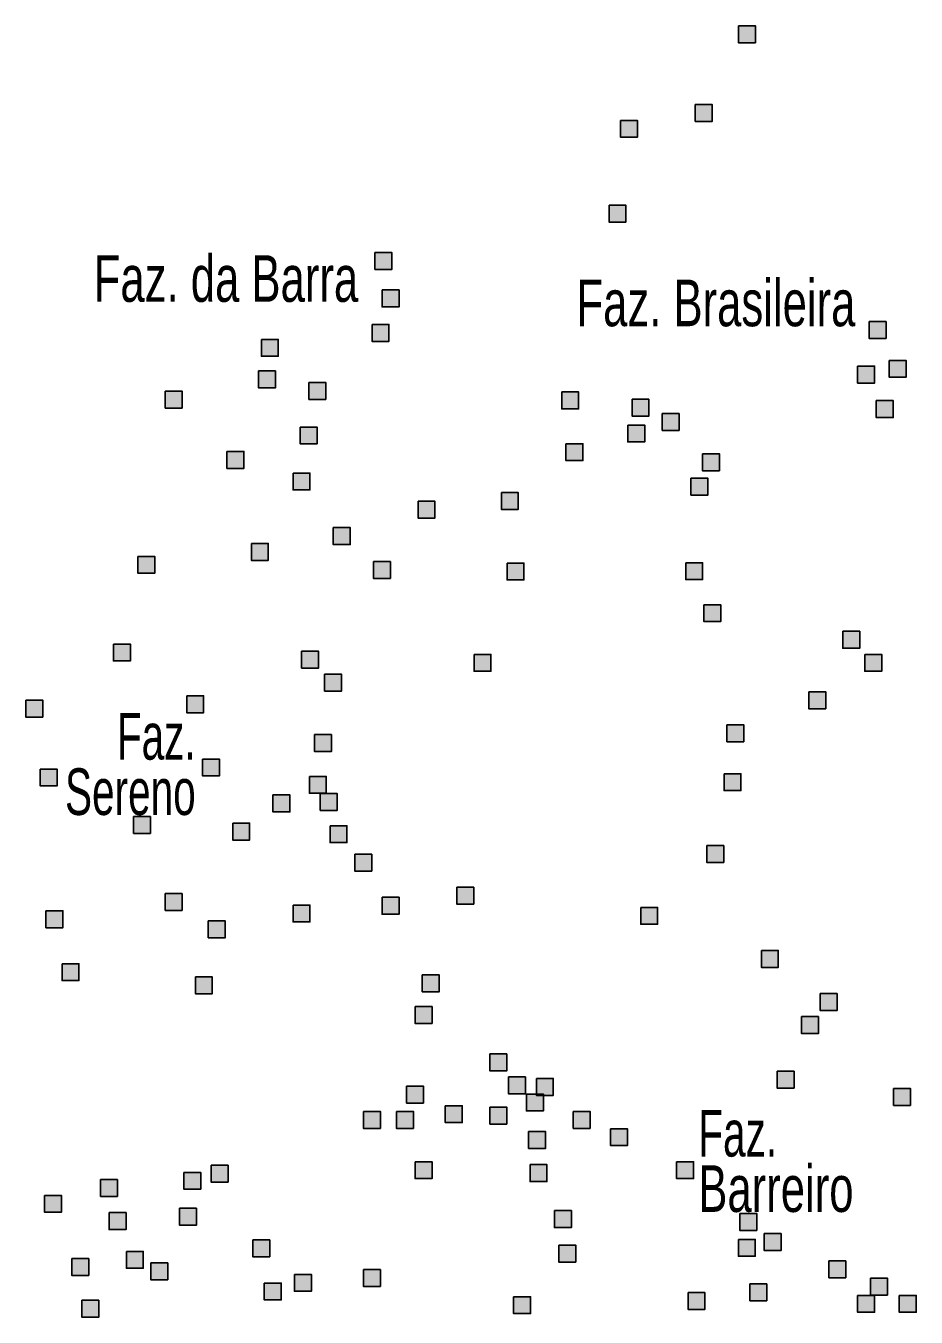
# Model space of a CAD drawing. Extents: x 445.4 to 500, y 8728.7 to 8784.
# Drawn here: x 488.568 to 491.623, y 8728.707 to 8733.138 of the extents above; entities that cross this region are included whole.
import ezdxf
from ezdxf.enums import TextEntityAlignment as Align

# ---------------------------------------------------------------- set-up
doc = ezdxf.new("R2010")
doc.units = 0
doc.header["$LTSCALE"] = 0.064
doc.layers.add('2', color=7, linetype='Continuous', lineweight=25)
doc.layers.add('61', color=7, linetype='Continuous')

msp = doc.modelspace()

# ---------------------------------------------------------------- hatches: boundary and pattern name
at = {"layer": '2'}
for points in [[(491.0138, 8733.1381), (491.0718, 8733.1381), (491.0718, 8733.0801), (491.0138, 8733.0801)], [(490.8656, 8732.868), (490.9236, 8732.868), (490.9236, 8732.81), (490.8656, 8732.81)], [(490.6093, 8732.8137), (490.6673, 8732.8137), (490.6673, 8732.7557), (490.6093, 8732.7557)], [(490.5698, 8732.5227), (490.6278, 8732.5227), (490.6278, 8732.4647), (490.5698, 8732.4647)], [(489.7664, 8732.36), (489.8244, 8732.36), (489.8244, 8732.302), (489.7664, 8732.302)], [(489.791, 8732.2318), (489.849, 8732.2318), (489.849, 8732.1738), (489.791, 8732.1738)], [(491.462, 8732.1233), (491.52, 8732.1233), (491.52, 8732.0653), (491.462, 8732.0653)], [(489.7565, 8732.1134), (489.8145, 8732.1134), (489.8145, 8732.0554), (489.7565, 8732.0554)], [(489.3769, 8732.0622), (489.4349, 8732.0622), (489.4349, 8732.0042), (489.3769, 8732.0042)], [(491.531, 8731.9901), (491.589, 8731.9901), (491.589, 8731.9321), (491.531, 8731.9321)], [(489.3671, 8731.9537), (489.4251, 8731.9537), (489.4251, 8731.8957), (489.3671, 8731.8957)], [(491.4226, 8731.9704), (491.4806, 8731.9704), (491.4806, 8731.9124), (491.4226, 8731.9124)], [(489.5396, 8731.9142), (489.5976, 8731.9142), (489.5976, 8731.8562), (489.5396, 8731.8562)], [(489.0467, 8731.8846), (489.1047, 8731.8846), (489.1047, 8731.8266), (489.0467, 8731.8266)], [(490.4072, 8731.8816), (490.4652, 8731.8816), (490.4652, 8731.8236), (490.4072, 8731.8236)], [(490.6487, 8731.857), (490.7067, 8731.857), (490.7067, 8731.799), (490.6487, 8731.799)], [(491.4867, 8731.852), (491.5447, 8731.852), (491.5447, 8731.794), (491.4867, 8731.794)], [(490.7522, 8731.8076), (490.8102, 8731.8076), (490.8102, 8731.7496), (490.7522, 8731.7496)], [(489.51, 8731.7613), (489.568, 8731.7613), (489.568, 8731.7033), (489.51, 8731.7033)], [(490.6339, 8731.7682), (490.6919, 8731.7682), (490.6919, 8731.7102), (490.6339, 8731.7102)], [(490.4219, 8731.7041), (490.4799, 8731.7041), (490.4799, 8731.6461), (490.4219, 8731.6461)], [(489.2586, 8731.6775), (489.3166, 8731.6775), (489.3166, 8731.6195), (489.2586, 8731.6195)], [(490.8902, 8731.6696), (490.9482, 8731.6696), (490.9482, 8731.6116), (490.8902, 8731.6116)], [(489.4854, 8731.6035), (489.5434, 8731.6035), (489.5434, 8731.5455), (489.4854, 8731.5455)], [(490.8508, 8731.5857), (490.9088, 8731.5857), (490.9088, 8731.5277), (490.8508, 8731.5277)], [(489.9142, 8731.5068), (489.9722, 8731.5068), (489.9722, 8731.4488), (489.9142, 8731.4488)], [(490.2001, 8731.5364), (490.2581, 8731.5364), (490.2581, 8731.4784), (490.2001, 8731.4784)], [(489.6234, 8731.4161), (489.6814, 8731.4161), (489.6814, 8731.3581), (489.6234, 8731.3581)], [(489.3424, 8731.3619), (489.4004, 8731.3619), (489.4004, 8731.3039), (489.3424, 8731.3039)], [(488.953, 8731.3175), (489.011, 8731.3175), (489.011, 8731.2595), (488.953, 8731.2595)], [(489.7614, 8731.2997), (489.8194, 8731.2997), (489.8194, 8731.2417), (489.7614, 8731.2417)], [(490.2198, 8731.2948), (490.2778, 8731.2948), (490.2778, 8731.2368), (490.2198, 8731.2368)], [(490.8329, 8731.2957), (490.8909, 8731.2957), (490.8909, 8731.2377), (490.8329, 8731.2377)], [(490.8952, 8731.1517), (490.9532, 8731.1517), (490.9532, 8731.0937), (490.8952, 8731.0937)], [(491.3717, 8731.0605), (491.4297, 8731.0605), (491.4297, 8731.0025), (491.3717, 8731.0025)], [(488.8692, 8731.0166), (488.9272, 8731.0166), (488.9272, 8730.9586), (488.8692, 8730.9586)], [(489.5149, 8730.992), (489.5729, 8730.992), (489.5729, 8730.934), (489.5149, 8730.934)], [(490.1065, 8730.9811), (490.1645, 8730.9811), (490.1645, 8730.9231), (490.1065, 8730.9231)], [(491.4472, 8730.9811), (491.5052, 8730.9811), (491.5052, 8730.9231), (491.4472, 8730.9231)], [(489.5938, 8730.9131), (489.6518, 8730.9131), (489.6518, 8730.8551), (489.5938, 8730.8551)], [(489.1206, 8730.8391), (489.1786, 8730.8391), (489.1786, 8730.7811), (489.1206, 8730.7811)], [(491.255, 8730.8529), (491.313, 8730.8529), (491.313, 8730.7949), (491.255, 8730.7949)], [(488.5685, 8730.8243), (488.6265, 8730.8243), (488.6265, 8730.7663), (488.5685, 8730.7663)], [(489.5593, 8730.7059), (489.6173, 8730.7059), (489.6173, 8730.6479), (489.5593, 8730.6479)], [(490.974, 8730.7395), (491.032, 8730.7395), (491.032, 8730.6815), (490.974, 8730.6815)], [(489.1748, 8730.6221), (489.2328, 8730.6221), (489.2328, 8730.5641), (489.1748, 8730.5641)], [(488.6178, 8730.5876), (488.6758, 8730.5876), (488.6758, 8730.5296), (488.6178, 8730.5296)], [(489.5414, 8730.5627), (489.5994, 8730.5627), (489.5994, 8730.5047), (489.5414, 8730.5047)], [(490.9642, 8730.5718), (491.0222, 8730.5718), (491.0222, 8730.5138), (490.9642, 8730.5138)], [(489.4164, 8730.4988), (489.4744, 8730.4988), (489.4744, 8730.4408), (489.4164, 8730.4408)], [(489.579, 8730.5037), (489.637, 8730.5037), (489.637, 8730.4457), (489.579, 8730.4457)], [(488.9382, 8730.4248), (488.9962, 8730.4248), (488.9962, 8730.3668), (488.9382, 8730.3668)], [(489.2783, 8730.4022), (489.3363, 8730.4022), (489.3363, 8730.3442), (489.2783, 8730.3442)], [(489.6124, 8730.3932), (489.6704, 8730.3932), (489.6704, 8730.3352), (489.6124, 8730.3352)], [(490.905, 8730.3252), (490.963, 8730.3252), (490.963, 8730.2672), (490.905, 8730.2672)], [(489.6973, 8730.2956), (489.7553, 8730.2956), (489.7553, 8730.2376), (489.6973, 8730.2376)], [(490.0473, 8730.1822), (490.1053, 8730.1822), (490.1053, 8730.1242), (490.0473, 8730.1242)], [(489.0467, 8730.1605), (489.1047, 8730.1605), (489.1047, 8730.1025), (489.0467, 8730.1025)], [(489.791, 8730.1477), (489.849, 8730.1477), (489.849, 8730.0897), (489.791, 8730.0897)], [(488.6375, 8730.1013), (488.6955, 8730.1013), (488.6955, 8730.0433), (488.6375, 8730.0433)], [(489.4854, 8730.1211), (489.5434, 8730.1211), (489.5434, 8730.0631), (489.4854, 8730.0631)], [(490.6783, 8730.1131), (490.7363, 8730.1131), (490.7363, 8730.0551), (490.6783, 8730.0551)], [(489.1945, 8730.0668), (489.2525, 8730.0668), (489.2525, 8730.0088), (489.1945, 8730.0088)], [(491.0923, 8729.9652), (491.1503, 8729.9652), (491.1503, 8729.9072), (491.0923, 8729.9072)], [(488.6929, 8729.9198), (488.7509, 8729.9198), (488.7509, 8729.8618), (488.6929, 8729.8618)], [(489.1502, 8729.8745), (489.2082, 8729.8745), (489.2082, 8729.8165), (489.1502, 8729.8165)], [(489.929, 8729.8814), (489.987, 8729.8814), (489.987, 8729.8234), (489.929, 8729.8234)], [(491.2944, 8729.8172), (491.3524, 8729.8172), (491.3524, 8729.7592), (491.2944, 8729.7592)], [(489.9044, 8729.7729), (489.9624, 8729.7729), (489.9624, 8729.7149), (489.9044, 8729.7149)], [(491.2303, 8729.7383), (491.2883, 8729.7383), (491.2883, 8729.6803), (491.2303, 8729.6803)], [(490.1607, 8729.6101), (490.2187, 8729.6101), (490.2187, 8729.5521), (490.1607, 8729.5521)], [(490.2248, 8729.5312), (490.2828, 8729.5312), (490.2828, 8729.4732), (490.2248, 8729.4732)], [(490.3204, 8729.526), (490.3784, 8729.526), (490.3784, 8729.468), (490.3204, 8729.468)], [(491.1465, 8729.5509), (491.2045, 8729.5509), (491.2045, 8729.4929), (491.1465, 8729.4929)], [(489.8748, 8729.4996), (489.9328, 8729.4996), (489.9328, 8729.4416), (489.8748, 8729.4416)], [(490.2862, 8729.4726), (490.3442, 8729.4726), (490.3442, 8729.4146), (490.2862, 8729.4146)], [(491.5458, 8729.4918), (491.6038, 8729.4918), (491.6038, 8729.4338), (491.5458, 8729.4338)], [(490.0079, 8729.4326), (490.0659, 8729.4326), (490.0659, 8729.3746), (490.0079, 8729.3746)], [(490.1607, 8729.4276), (490.2187, 8729.4276), (490.2187, 8729.3696), (490.1607, 8729.3696)], [(489.7269, 8729.4128), (489.7849, 8729.4128), (489.7849, 8729.3548), (489.7269, 8729.3548)], [(489.8403, 8729.4128), (489.8983, 8729.4128), (489.8983, 8729.3548), (489.8403, 8729.3548)], [(490.4466, 8729.4128), (490.5046, 8729.4128), (490.5046, 8729.3548), (490.4466, 8729.3548)], [(490.2938, 8729.3438), (490.3518, 8729.3438), (490.3518, 8729.2858), (490.2938, 8729.2858)], [(490.5748, 8729.3537), (490.6328, 8729.3537), (490.6328, 8729.2957), (490.5748, 8729.2957)], [(489.1107, 8729.2038), (489.1687, 8729.2038), (489.1687, 8729.1458), (489.1107, 8729.1458)], [(489.2044, 8729.2284), (489.2624, 8729.2284), (489.2624, 8729.1704), (489.2044, 8729.1704)], [(489.9044, 8729.2402), (489.9624, 8729.2402), (489.9624, 8729.1822), (489.9044, 8729.1822)], [(490.2987, 8729.2304), (490.3567, 8729.2304), (490.3567, 8729.1724), (490.2987, 8729.1724)], [(490.8015, 8729.2402), (490.8595, 8729.2402), (490.8595, 8729.1822), (490.8015, 8729.1822)], [(488.8248, 8729.1791), (488.8828, 8729.1791), (488.8828, 8729.1211), (488.8248, 8729.1211)], [(488.6326, 8729.1249), (488.6906, 8729.1249), (488.6906, 8729.0669), (488.6326, 8729.0669)], [(488.8544, 8729.0657), (488.9124, 8729.0657), (488.9124, 8729.0077), (488.8544, 8729.0077)], [(489.096, 8729.0805), (489.154, 8729.0805), (489.154, 8729.0225), (489.096, 8729.0225)], [(490.3825, 8729.0726), (490.4405, 8729.0726), (490.4405, 8729.0146), (490.3825, 8729.0146)], [(491.0184, 8729.0627), (491.0764, 8729.0627), (491.0764, 8729.0047), (491.0184, 8729.0047)], [(491.1022, 8728.9936), (491.1602, 8728.9936), (491.1602, 8728.9356), (491.1022, 8728.9356)], [(488.9136, 8728.9325), (488.9716, 8728.9325), (488.9716, 8728.8745), (488.9136, 8728.8745)], [(489.3473, 8728.972), (489.4053, 8728.972), (489.4053, 8728.914), (489.3473, 8728.914)], [(490.3973, 8728.9542), (490.4553, 8728.9542), (490.4553, 8728.8962), (490.3973, 8728.8962)], [(491.0135, 8728.9739), (491.0715, 8728.9739), (491.0715, 8728.9159), (491.0135, 8728.9159)], [(488.7263, 8728.9079), (488.7843, 8728.9079), (488.7843, 8728.8499), (488.7263, 8728.8499)], [(488.9974, 8728.8931), (489.0554, 8728.8931), (489.0554, 8728.8351), (488.9974, 8728.8351)], [(491.324, 8728.8999), (491.382, 8728.8999), (491.382, 8728.8419), (491.324, 8728.8419)], [(489.4903, 8728.8536), (489.5483, 8728.8536), (489.5483, 8728.7956), (489.4903, 8728.7956)], [(489.7269, 8728.8704), (489.7849, 8728.8704), (489.7849, 8728.8124), (489.7269, 8728.8124)], [(489.3868, 8728.824), (489.4448, 8728.824), (489.4448, 8728.766), (489.3868, 8728.766)], [(491.0529, 8728.821), (491.1109, 8728.821), (491.1109, 8728.763), (491.0529, 8728.763)], [(491.4669, 8728.8408), (491.5249, 8728.8408), (491.5249, 8728.7828), (491.4669, 8728.7828)], [(488.7608, 8728.7649), (488.8188, 8728.7649), (488.8188, 8728.7069), (488.7608, 8728.7069)], [(490.2422, 8728.777), (490.3002, 8728.777), (490.3002, 8728.719), (490.2422, 8728.719)], [(490.8409, 8728.7914), (490.8989, 8728.7914), (490.8989, 8728.7334), (490.8409, 8728.7334)], [(491.4226, 8728.7816), (491.4806, 8728.7816), (491.4806, 8728.7236), (491.4226, 8728.7236)], [(491.5655, 8728.7816), (491.6235, 8728.7816), (491.6235, 8728.7236), (491.5655, 8728.7236)]]:
    msp.add_hatch(color=256, dxfattribs=at).paths.add_polyline_path(points)

# ---------------------------------------------------------------- linework, layer by layer
for points in [[(491.0138, 8733.1381), (491.0718, 8733.1381), (491.0718, 8733.0801), (491.0138, 8733.0801)], [(490.8656, 8732.868), (490.9236, 8732.868), (490.9236, 8732.81), (490.8656, 8732.81)], [(490.6093, 8732.8137), (490.6673, 8732.8137), (490.6673, 8732.7557), (490.6093, 8732.7557)], [(490.5698, 8732.5227), (490.6278, 8732.5227), (490.6278, 8732.4647), (490.5698, 8732.4647)], [(489.7664, 8732.36), (489.8244, 8732.36), (489.8244, 8732.302), (489.7664, 8732.302)], [(489.791, 8732.2318), (489.849, 8732.2318), (489.849, 8732.1738), (489.791, 8732.1738)], [(491.462, 8732.1233), (491.52, 8732.1233), (491.52, 8732.0653), (491.462, 8732.0653)], [(489.7565, 8732.1134), (489.8145, 8732.1134), (489.8145, 8732.0554), (489.7565, 8732.0554)], [(489.3769, 8732.0622), (489.4349, 8732.0622), (489.4349, 8732.0042), (489.3769, 8732.0042)], [(491.531, 8731.9901), (491.589, 8731.9901), (491.589, 8731.9321), (491.531, 8731.9321)], [(489.3671, 8731.9537), (489.4251, 8731.9537), (489.4251, 8731.8957), (489.3671, 8731.8957)], [(491.4226, 8731.9704), (491.4806, 8731.9704), (491.4806, 8731.9124), (491.4226, 8731.9124)], [(489.5396, 8731.9142), (489.5976, 8731.9142), (489.5976, 8731.8562), (489.5396, 8731.8562)], [(489.0467, 8731.8846), (489.1047, 8731.8846), (489.1047, 8731.8266), (489.0467, 8731.8266)], [(490.4072, 8731.8816), (490.4652, 8731.8816), (490.4652, 8731.8236), (490.4072, 8731.8236)], [(490.6487, 8731.857), (490.7067, 8731.857), (490.7067, 8731.799), (490.6487, 8731.799)], [(491.4867, 8731.852), (491.5447, 8731.852), (491.5447, 8731.794), (491.4867, 8731.794)], [(490.7522, 8731.8076), (490.8102, 8731.8076), (490.8102, 8731.7496), (490.7522, 8731.7496)], [(489.51, 8731.7613), (489.568, 8731.7613), (489.568, 8731.7033), (489.51, 8731.7033)], [(490.6339, 8731.7682), (490.6919, 8731.7682), (490.6919, 8731.7102), (490.6339, 8731.7102)], [(490.4219, 8731.7041), (490.4799, 8731.7041), (490.4799, 8731.6461), (490.4219, 8731.6461)], [(489.2586, 8731.6775), (489.3166, 8731.6775), (489.3166, 8731.6195), (489.2586, 8731.6195)], [(490.8902, 8731.6696), (490.9482, 8731.6696), (490.9482, 8731.6116), (490.8902, 8731.6116)], [(489.4854, 8731.6035), (489.5434, 8731.6035), (489.5434, 8731.5455), (489.4854, 8731.5455)], [(490.8508, 8731.5857), (490.9088, 8731.5857), (490.9088, 8731.5277), (490.8508, 8731.5277)], [(489.9142, 8731.5068), (489.9722, 8731.5068), (489.9722, 8731.4488), (489.9142, 8731.4488)], [(490.2001, 8731.5364), (490.2581, 8731.5364), (490.2581, 8731.4784), (490.2001, 8731.4784)], [(489.6234, 8731.4161), (489.6814, 8731.4161), (489.6814, 8731.3581), (489.6234, 8731.3581)], [(489.3424, 8731.3619), (489.4004, 8731.3619), (489.4004, 8731.3039), (489.3424, 8731.3039)], [(488.953, 8731.3175), (489.011, 8731.3175), (489.011, 8731.2595), (488.953, 8731.2595)], [(489.7614, 8731.2997), (489.8194, 8731.2997), (489.8194, 8731.2417), (489.7614, 8731.2417)], [(490.2198, 8731.2948), (490.2778, 8731.2948), (490.2778, 8731.2368), (490.2198, 8731.2368)], [(490.8329, 8731.2957), (490.8909, 8731.2957), (490.8909, 8731.2377), (490.8329, 8731.2377)], [(490.8952, 8731.1517), (490.9532, 8731.1517), (490.9532, 8731.0937), (490.8952, 8731.0937)], [(491.3717, 8731.0605), (491.4297, 8731.0605), (491.4297, 8731.0025), (491.3717, 8731.0025)], [(488.8692, 8731.0166), (488.9272, 8731.0166), (488.9272, 8730.9586), (488.8692, 8730.9586)], [(489.5149, 8730.992), (489.5729, 8730.992), (489.5729, 8730.934), (489.5149, 8730.934)], [(490.1065, 8730.9811), (490.1645, 8730.9811), (490.1645, 8730.9231), (490.1065, 8730.9231)], [(491.4472, 8730.9811), (491.5052, 8730.9811), (491.5052, 8730.9231), (491.4472, 8730.9231)], [(489.5938, 8730.9131), (489.6518, 8730.9131), (489.6518, 8730.8551), (489.5938, 8730.8551)], [(489.1206, 8730.8391), (489.1786, 8730.8391), (489.1786, 8730.7811), (489.1206, 8730.7811)], [(491.255, 8730.8529), (491.313, 8730.8529), (491.313, 8730.7949), (491.255, 8730.7949)], [(488.5685, 8730.8243), (488.6265, 8730.8243), (488.6265, 8730.7663), (488.5685, 8730.7663)], [(489.5593, 8730.7059), (489.6173, 8730.7059), (489.6173, 8730.6479), (489.5593, 8730.6479)], [(490.974, 8730.7395), (491.032, 8730.7395), (491.032, 8730.6815), (490.974, 8730.6815)], [(489.1748, 8730.6221), (489.2328, 8730.6221), (489.2328, 8730.5641), (489.1748, 8730.5641)], [(488.6178, 8730.5876), (488.6758, 8730.5876), (488.6758, 8730.5296), (488.6178, 8730.5296)], [(489.5414, 8730.5627), (489.5994, 8730.5627), (489.5994, 8730.5047), (489.5414, 8730.5047)], [(490.9642, 8730.5718), (491.0222, 8730.5718), (491.0222, 8730.5138), (490.9642, 8730.5138)], [(489.4164, 8730.4988), (489.4744, 8730.4988), (489.4744, 8730.4408), (489.4164, 8730.4408)], [(489.579, 8730.5037), (489.637, 8730.5037), (489.637, 8730.4457), (489.579, 8730.4457)], [(488.9382, 8730.4248), (488.9962, 8730.4248), (488.9962, 8730.3668), (488.9382, 8730.3668)], [(489.2783, 8730.4022), (489.3363, 8730.4022), (489.3363, 8730.3442), (489.2783, 8730.3442)], [(489.6124, 8730.3932), (489.6704, 8730.3932), (489.6704, 8730.3352), (489.6124, 8730.3352)], [(490.905, 8730.3252), (490.963, 8730.3252), (490.963, 8730.2672), (490.905, 8730.2672)], [(489.6973, 8730.2956), (489.7553, 8730.2956), (489.7553, 8730.2376), (489.6973, 8730.2376)], [(490.0473, 8730.1822), (490.1053, 8730.1822), (490.1053, 8730.1242), (490.0473, 8730.1242)], [(489.0467, 8730.1605), (489.1047, 8730.1605), (489.1047, 8730.1025), (489.0467, 8730.1025)], [(489.791, 8730.1477), (489.849, 8730.1477), (489.849, 8730.0897), (489.791, 8730.0897)], [(488.6375, 8730.1013), (488.6955, 8730.1013), (488.6955, 8730.0433), (488.6375, 8730.0433)], [(489.4854, 8730.1211), (489.5434, 8730.1211), (489.5434, 8730.0631), (489.4854, 8730.0631)], [(490.6783, 8730.1131), (490.7363, 8730.1131), (490.7363, 8730.0551), (490.6783, 8730.0551)], [(489.1945, 8730.0668), (489.2525, 8730.0668), (489.2525, 8730.0088), (489.1945, 8730.0088)], [(491.0923, 8729.9652), (491.1503, 8729.9652), (491.1503, 8729.9072), (491.0923, 8729.9072)], [(488.6929, 8729.9198), (488.7509, 8729.9198), (488.7509, 8729.8618), (488.6929, 8729.8618)], [(489.1502, 8729.8745), (489.2082, 8729.8745), (489.2082, 8729.8165), (489.1502, 8729.8165)], [(489.929, 8729.8814), (489.987, 8729.8814), (489.987, 8729.8234), (489.929, 8729.8234)], [(491.2944, 8729.8172), (491.3524, 8729.8172), (491.3524, 8729.7592), (491.2944, 8729.7592)], [(489.9044, 8729.7729), (489.9624, 8729.7729), (489.9624, 8729.7149), (489.9044, 8729.7149)], [(491.2303, 8729.7383), (491.2883, 8729.7383), (491.2883, 8729.6803), (491.2303, 8729.6803)], [(490.1607, 8729.6101), (490.2187, 8729.6101), (490.2187, 8729.5521), (490.1607, 8729.5521)], [(490.2248, 8729.5312), (490.2828, 8729.5312), (490.2828, 8729.4732), (490.2248, 8729.4732)], [(490.3204, 8729.526), (490.3784, 8729.526), (490.3784, 8729.468), (490.3204, 8729.468)], [(491.1465, 8729.5509), (491.2045, 8729.5509), (491.2045, 8729.4929), (491.1465, 8729.4929)], [(489.8748, 8729.4996), (489.9328, 8729.4996), (489.9328, 8729.4416), (489.8748, 8729.4416)], [(490.2862, 8729.4726), (490.3442, 8729.4726), (490.3442, 8729.4146), (490.2862, 8729.4146)], [(491.5458, 8729.4918), (491.6038, 8729.4918), (491.6038, 8729.4338), (491.5458, 8729.4338)], [(490.0079, 8729.4326), (490.0659, 8729.4326), (490.0659, 8729.3746), (490.0079, 8729.3746)], [(490.1607, 8729.4276), (490.2187, 8729.4276), (490.2187, 8729.3696), (490.1607, 8729.3696)], [(489.7269, 8729.4128), (489.7849, 8729.4128), (489.7849, 8729.3548), (489.7269, 8729.3548)], [(489.8403, 8729.4128), (489.8983, 8729.4128), (489.8983, 8729.3548), (489.8403, 8729.3548)], [(490.4466, 8729.4128), (490.5046, 8729.4128), (490.5046, 8729.3548), (490.4466, 8729.3548)], [(490.2938, 8729.3438), (490.3518, 8729.3438), (490.3518, 8729.2858), (490.2938, 8729.2858)], [(490.5748, 8729.3537), (490.6328, 8729.3537), (490.6328, 8729.2957), (490.5748, 8729.2957)], [(489.1107, 8729.2038), (489.1687, 8729.2038), (489.1687, 8729.1458), (489.1107, 8729.1458)], [(489.2044, 8729.2284), (489.2624, 8729.2284), (489.2624, 8729.1704), (489.2044, 8729.1704)], [(489.9044, 8729.2402), (489.9624, 8729.2402), (489.9624, 8729.1822), (489.9044, 8729.1822)], [(490.2987, 8729.2304), (490.3567, 8729.2304), (490.3567, 8729.1724), (490.2987, 8729.1724)], [(490.8015, 8729.2402), (490.8595, 8729.2402), (490.8595, 8729.1822), (490.8015, 8729.1822)], [(488.8248, 8729.1791), (488.8828, 8729.1791), (488.8828, 8729.1211), (488.8248, 8729.1211)], [(488.6326, 8729.1249), (488.6906, 8729.1249), (488.6906, 8729.0669), (488.6326, 8729.0669)], [(488.8544, 8729.0657), (488.9124, 8729.0657), (488.9124, 8729.0077), (488.8544, 8729.0077)], [(489.096, 8729.0805), (489.154, 8729.0805), (489.154, 8729.0225), (489.096, 8729.0225)], [(490.3825, 8729.0726), (490.4405, 8729.0726), (490.4405, 8729.0146), (490.3825, 8729.0146)], [(491.0184, 8729.0627), (491.0764, 8729.0627), (491.0764, 8729.0047), (491.0184, 8729.0047)], [(491.1022, 8728.9936), (491.1602, 8728.9936), (491.1602, 8728.9356), (491.1022, 8728.9356)], [(488.9136, 8728.9325), (488.9716, 8728.9325), (488.9716, 8728.8745), (488.9136, 8728.8745)], [(489.3473, 8728.972), (489.4053, 8728.972), (489.4053, 8728.914), (489.3473, 8728.914)], [(490.3973, 8728.9542), (490.4553, 8728.9542), (490.4553, 8728.8962), (490.3973, 8728.8962)], [(491.0135, 8728.9739), (491.0715, 8728.9739), (491.0715, 8728.9159), (491.0135, 8728.9159)], [(488.7263, 8728.9079), (488.7843, 8728.9079), (488.7843, 8728.8499), (488.7263, 8728.8499)], [(488.9974, 8728.8931), (489.0554, 8728.8931), (489.0554, 8728.8351), (488.9974, 8728.8351)], [(491.324, 8728.8999), (491.382, 8728.8999), (491.382, 8728.8419), (491.324, 8728.8419)], [(489.4903, 8728.8536), (489.5483, 8728.8536), (489.5483, 8728.7956), (489.4903, 8728.7956)], [(489.7269, 8728.8704), (489.7849, 8728.8704), (489.7849, 8728.8124), (489.7269, 8728.8124)], [(489.3868, 8728.824), (489.4448, 8728.824), (489.4448, 8728.766), (489.3868, 8728.766)], [(491.0529, 8728.821), (491.1109, 8728.821), (491.1109, 8728.763), (491.0529, 8728.763)], [(491.4669, 8728.8408), (491.5249, 8728.8408), (491.5249, 8728.7828), (491.4669, 8728.7828)], [(488.7608, 8728.7649), (488.8188, 8728.7649), (488.8188, 8728.7069), (488.7608, 8728.7069)], [(490.2422, 8728.777), (490.3002, 8728.777), (490.3002, 8728.719), (490.2422, 8728.719)], [(490.8409, 8728.7914), (490.8989, 8728.7914), (490.8989, 8728.7334), (490.8409, 8728.7334)], [(491.4226, 8728.7816), (491.4806, 8728.7816), (491.4806, 8728.7236), (491.4226, 8728.7236)], [(491.5655, 8728.7816), (491.6235, 8728.7816), (491.6235, 8728.7236), (491.5655, 8728.7236)]]:
    msp.add_lwpolyline(points, close=True, dxfattribs=at)

# ---------------------------------------------------------------- texts
at = {"layer": '61'}
for s, width, p in [('       Faz. da Barra', 0.7, (489.7089, 8732.191)), ('Faz.', 0.65, (489.1514, 8730.6202)), ('Sereno', 0.65, (489.1514, 8730.4302))]:
    msp.add_text(s, height=0.16, dxfattribs=dict(at, width=width)).set_placement(p, align=Align.RIGHT)
for s, width, p in [('Faz. Brasileira', 0.7, (490.4579, 8732.1073)), ('Faz.', 0.65, (490.8759, 8729.2581)), ('Barreiro', 0.7, (490.8759, 8729.0681))]:
    msp.add_text(s, height=0.16, dxfattribs=dict(at, width=width)).set_placement(p)

doc.saveas('drawing.dxf')
